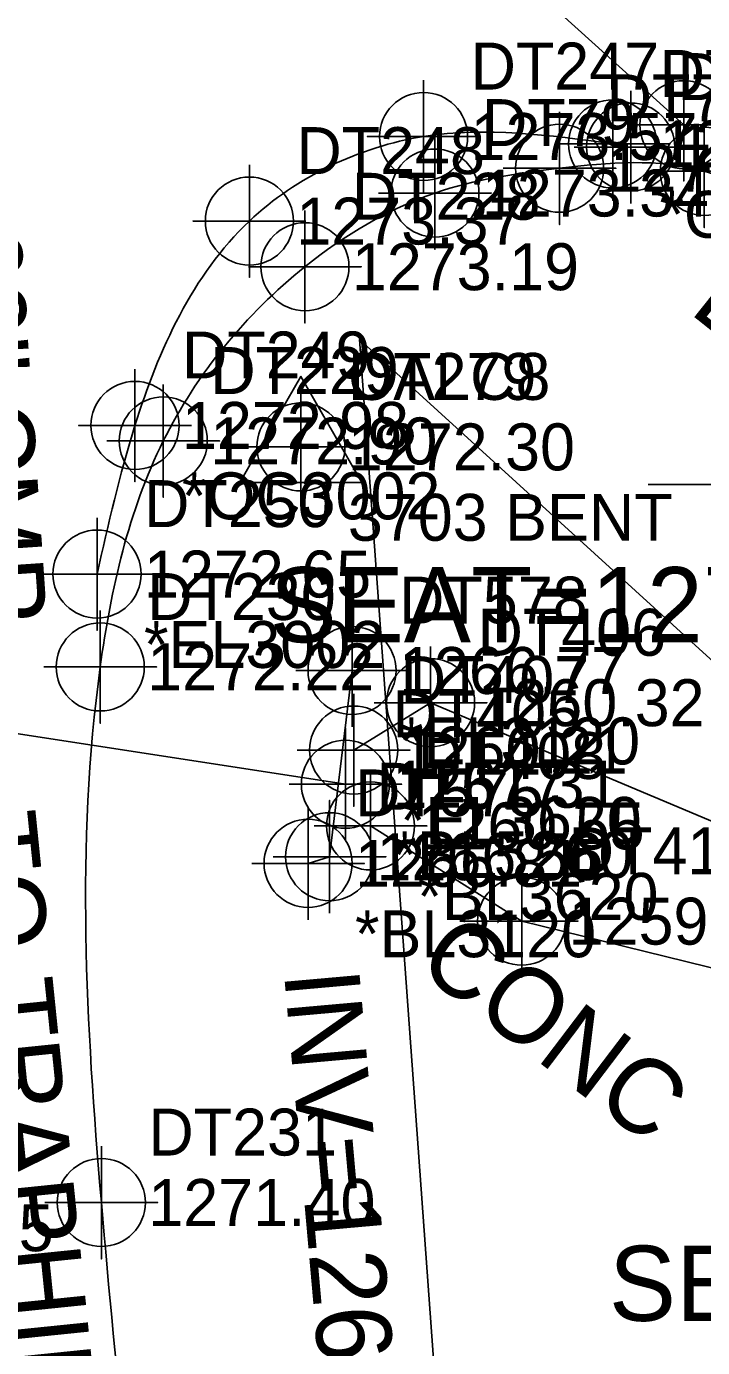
# Model space of a CAD drawing. Extents: x 1390773 to 1392296, y 959928 to 960736.
# Drawn here: x 1391507.3 to 1391543.3, y 960333 to 960403.3 of the extents above; entities that cross this region are included whole.
import ezdxf

# ---------------------------------------------------------------- set-up
doc = ezdxf.new("R2010")
doc.units = 0
for name, color, linetype in [('Cogo Default Point CELL', 7, 'Continuous'), ('COGO Default Point Elevation', 7, 'Continuous'), ('COGO Default Point Number', 7, 'Continuous'), ('Exist Hydro Jurisdictional Stream or Body of Water', 7, 'Continuous'), ('Exist Hydro Stream or Body of Water', 7, 'Continuous'), ('Exist Hydro Stream or Body of Water Cogo Comment', 7, 'Continuous'), ('Exist Hydro Stream or Body of Water Cogo Elevation', 7, 'Continuous'), ('Exist Hydro Stream or Body of Water Cogo Number', 7, 'Continuous'), ('Exist Hydro Stream or Body of Water Cogo Point CELL', 7, 'Continuous'), ('Exist Other Culture Located Object Text', 7, 'Continuous'), ('Exist Right of Way Line', 7, 'Continuous'), ('Exist Right of Way Monument CELL', 7, 'Continuous'), ('Exist Right of Way Monument Cogo Comment', 7, 'Continuous'), ('Exist Right of Way Monument Cogo Elevation', 7, 'Continuous'), ('Exist Right of Way Monument Cogo Number', 7, 'Continuous'), ('Exist Roads EOP', 7, 'Continuous'), ('Exist Roads EOP Cogo Elevation', 7, 'Continuous'), ('Exist Roads EOP Cogo Number', 7, 'Continuous'), ('Exist Roads EOP Cogo Point CELL', 7, 'Continuous'), ('Exist Roads EOP Text', 7, 'Continuous'), ('Exist Roads EOT', 7, 'Continuous'), ('Exist Roads EOT Cogo Comment', 7, 'Continuous'), ('Exist Roads EOT Cogo Elevation', 7, 'Continuous'), ('Exist Roads EOT Cogo Number', 7, 'Continuous'), ('Exist Roads EOT Cogo Point CELL', 7, 'Continuous'), ('Exist Structure Major Bridge Seat Top Elevation', 7, 'Continuous'), ('Exist Structure Minor Head and End Wall', 7, 'Continuous'), ('Exist Structure Minor Head and End Wall Cogo Comment', 7, 'Continuous'), ('Exist Structure Minor Head and End Wall Cogo Elevation', 7, 'Continuous'), ('Exist Structure Minor Head and End Wall Cogo Number', 7, 'Continuous'), ('Exist Structure Minor Head and End Wall Cogo Point CELL', 7, 'Continuous'), ('Exist Structure Minor Head and End Wall Text', 7, 'Continuous'), ('Exist Structure Minor Pipes CMP 60 Inch', 7, 'Continuous'), ('Exist Structure Minor Pipes CMP 60 Inch Cogo Comment', 7, 'Continuous'), ('Exist Structure Minor Pipes CMP 60 Inch Cogo Elevation', 7, 'Continuous'), ('Exist Structure Minor Pipes CMP 60 Inch Cogo Number', 7, 'Continuous'), ('Exist Structure Minor Pipes CMP 60 Inch Cogo Point CELL', 7, 'Continuous'), ('Exist Structure Minor Pipes CMP 60 Inch Invert', 7, 'Continuous'), ('Exist Structure Minor Pipes CMP 60 Inch Text', 7, 'Continuous'), ('Exist Utilities Telephone Pole CELL', 7, 'Continuous')]:
    doc.layers.add(name, color=color, linetype=linetype)

msp = doc.modelspace()

# ---------------------------------------------------------------- linework, layer by layer
at = {"layer": 'Cogo Default Point CELL'}
for points in [[(1391539.491, 960399.874), (1391539.491, 960396.874)], [(1391536.491, 960396.874), (1391539.491, 960396.874)], [(1391539.491, 960396.874), (1391542.491, 960396.874)], [(1391539.491, 960396.874), (1391539.491, 960393.874)], [(1391521.941, 960383.908), (1391521.941, 960380.908)], [(1391518.941, 960380.908), (1391521.941, 960380.908)], [(1391521.941, 960380.908), (1391524.941, 960380.908)], [(1391521.941, 960380.908), (1391521.941, 960377.908)]]:
    msp.add_lwpolyline(points, dxfattribs=at)
for centre in [(1391539.491, 960396.874), (1391521.941, 960380.908)]:
    msp.add_circle(centre, 2.344, dxfattribs=at)
at = {"layer": 'Exist Hydro Jurisdictional Stream or Body of Water'}
msp.add_lwpolyline([(1391525.646, 960360.725), (1391533.691, 960355.656), (1391551.222, 960351.349), (1391566.005, 960349.028), (1391587.602, 960346.087), (1391590.063, 960325.761), (1391581.908, 960284.337), (1391574.185, 960247.222), (1391569.673, 960235.504)], dxfattribs=at)
at = {"layer": 'Exist Hydro Stream or Body of Water'}
msp.add_lwpolyline([(1391589.108, 960351.82), (1391588.85, 960350.646), (1391564.84, 960352.852), (1391552.616, 960357.272), (1391528.84, 960367.287), (1391524.75, 960364.767)], dxfattribs=at)
at = {"layer": 'Exist Hydro Stream or Body of Water Cogo Point CELL'}
for points in [[(1391525.84, 960367.287), (1391531.84, 960367.287), (1391528.84, 960367.287), (1391528.84, 960364.287), (1391528.84, 960370.287)], [(1391521.75, 960364.767), (1391527.75, 960364.767), (1391524.75, 960364.767), (1391524.75, 960361.767), (1391524.75, 960367.767)], [(1391522.646, 960360.725), (1391528.646, 960360.725), (1391525.646, 960360.725), (1391525.646, 960357.725), (1391525.646, 960363.725)], [(1391530.691, 960355.656), (1391536.691, 960355.656), (1391533.691, 960355.656), (1391533.691, 960352.656), (1391533.691, 960358.656)]]:
    msp.add_lwpolyline(points, dxfattribs=at)
for centre in [(1391528.84, 960367.287), (1391524.75, 960364.767), (1391525.646, 960360.725), (1391533.691, 960355.656)]:
    msp.add_circle(centre, 2.344, dxfattribs=at)
at = {"layer": 'Exist Right of Way Line'}
for p, q in [((1391525.055, 960386.628), (1391657.467, 960265.902)), ((1391530.522, 960311.417), (1391525.055, 960386.628))]:
    msp.add_line(p, q, dxfattribs=at)
at = {"layer": 'Exist Right of Way Monument CELL'}
msp.add_line((1391521.941, 960380.908), (1391521.941, 960380.908), dxfattribs=at)
msp.add_lwpolyline([(1391518.692, 960379.019), (1391521.941, 960384.658), (1391525.189, 960379.018)], close=True, dxfattribs=at)
at = {"layer": 'Exist Roads EOP'}
msp.add_spline([(1391553.715, 960387.967), (1391548.413, 960392.843), (1391543.408, 960395.581), (1391535.709, 960395.746), (1391529.074, 960394.424), (1391522.155, 960390.501), (1391514.618, 960381.223), (1391511.262, 960369.19), (1391511.324, 960340.675), (1391514.177, 960312.818)], degree=3, dxfattribs=at)
at = {"layer": 'Exist Roads EOP Cogo Point CELL'}
for points in [[(1391535.709, 960398.746), (1391535.709, 960392.746), (1391535.709, 960395.746), (1391538.709, 960395.746), (1391532.709, 960395.746)], [(1391543.408, 960398.581), (1391543.408, 960392.581), (1391543.408, 960395.581), (1391546.408, 960395.581), (1391540.408, 960395.581)], [(1391529.074, 960397.424), (1391529.074, 960391.424), (1391529.074, 960394.424), (1391532.074, 960394.424), (1391526.074, 960394.424)], [(1391522.155, 960393.501), (1391522.155, 960387.501), (1391522.155, 960390.501), (1391525.155, 960390.501), (1391519.155, 960390.501)], [(1391514.618, 960384.223), (1391514.618, 960378.223), (1391514.618, 960381.223), (1391517.618, 960381.223), (1391511.618, 960381.223)], [(1391511.262, 960372.19), (1391511.262, 960366.19), (1391511.262, 960369.19), (1391514.262, 960369.19), (1391508.262, 960369.19)], [(1391511.324, 960343.675), (1391511.324, 960337.675), (1391511.324, 960340.675), (1391514.324, 960340.675), (1391508.324, 960340.675)]]:
    msp.add_lwpolyline(points, dxfattribs=at)
for centre in [(1391535.709, 960395.746), (1391543.408, 960395.581), (1391529.074, 960394.424), (1391522.155, 960390.501), (1391514.618, 960381.223), (1391511.262, 960369.19), (1391511.324, 960340.675)]:
    msp.add_circle(centre, 2.344, dxfattribs=at)
at = {"layer": 'Exist Roads EOT'}
msp.add_lwpolyline([(1391542.319, 960398.059), (1391518.576, 960419.517), (1391494.192, 960441.585), (1391465.739, 960467.932), (1391455.599, 960477.451)], dxfattribs=at)
msp.add_spline([(1391511.094, 960374.137), (1391513.113, 960382.05), (1391519.201, 960392.933), (1391528.47, 960397.434), (1391538.533, 960397.042)], degree=3, dxfattribs=at)
at = {"layer": 'Exist Roads EOT Cogo Point CELL'}
for points in [[(1391542.319, 960401.059), (1391542.319, 960395.059), (1391542.319, 960398.059), (1391539.319, 960398.059), (1391545.319, 960398.059)], [(1391528.47, 960400.434), (1391528.47, 960394.434), (1391528.47, 960397.434), (1391525.47, 960397.434), (1391531.47, 960397.434)], [(1391538.533, 960400.042), (1391538.533, 960394.042), (1391538.533, 960397.042), (1391535.533, 960397.042), (1391541.533, 960397.042)], [(1391519.201, 960395.933), (1391519.201, 960389.933), (1391519.201, 960392.933), (1391516.201, 960392.933), (1391522.201, 960392.933)], [(1391513.113, 960385.05), (1391513.113, 960379.05), (1391513.113, 960382.05), (1391510.113, 960382.05), (1391516.113, 960382.05)], [(1391511.094, 960377.137), (1391511.094, 960371.137), (1391511.094, 960374.137), (1391508.094, 960374.137), (1391514.094, 960374.137)]]:
    msp.add_lwpolyline(points, dxfattribs=at)
for centre in [(1391542.319, 960398.059), (1391528.47, 960397.434), (1391538.533, 960397.042), (1391519.201, 960392.933), (1391513.113, 960382.05), (1391511.094, 960374.137)]:
    msp.add_circle(centre, 2.344, dxfattribs=at)
at = {"layer": 'Exist Structure Minor Head and End Wall'}
msp.add_lwpolyline([(1391522.324, 960358.734), (1391523.466, 960359.087), (1391524.665, 960369.001)], dxfattribs=at)
at = {"layer": 'Exist Structure Minor Head and End Wall Cogo Point CELL'}
for points in [[(1391521.665, 960369.001), (1391527.665, 960369.001), (1391524.665, 960369.001), (1391524.665, 960372.001), (1391524.665, 960366.001)], [(1391520.466, 960359.087), (1391526.466, 960359.087), (1391523.466, 960359.087), (1391523.466, 960362.087), (1391523.466, 960356.087)], [(1391519.324, 960358.734), (1391525.324, 960358.734), (1391522.324, 960358.734), (1391522.324, 960361.734), (1391522.324, 960355.734)]]:
    msp.add_lwpolyline(points, dxfattribs=at)
for centre in [(1391524.665, 960369.001), (1391523.466, 960359.087), (1391522.324, 960358.734)]:
    msp.add_circle(centre, 2.344, dxfattribs=at)
at = {"layer": 'Exist Structure Minor Pipes CMP 60 Inch'}
msp.add_line((1391524.311, 960362.945), (1391475.363, 960370.472), dxfattribs=at)
at = {"layer": 'Exist Structure Minor Pipes CMP 60 Inch Cogo Point CELL'}
msp.add_lwpolyline([(1391524.311, 960365.945), (1391524.311, 960359.945), (1391524.311, 960362.945), (1391527.311, 960362.945), (1391521.311, 960362.945)], dxfattribs=at)
msp.add_circle((1391524.311, 960362.945), 2.344, dxfattribs=at)
at = {"layer": 'Exist Utilities Telephone Pole CELL'}
msp.add_line((1391540.422, 960378.907), (1391551.759, 960378.907), dxfattribs=at)

# ---------------------------------------------------------------- texts
at = {"layer": 'COGO Default Point Elevation'}
for s, p in [('1273.69', (1391541.991, 960395.624)), ('1272.30', (1391524.441, 960379.658))]:
    msp.add_text(s, height=2.5, dxfattribs=at).set_placement(p)
at = {"layer": 'COGO Default Point Number'}
for s, p in [('DT245', (1391541.991, 960399.374)), ('CALC8', (1391524.441, 960383.408))]:
    msp.add_text(s, height=2.5, dxfattribs=at).set_placement(p)
at = {"layer": 'Exist Hydro Stream or Body of Water Cogo Comment'}
for s, p in [('*EL3620', (1391527.25, 960359.767)), ('*BL3620', (1391528.146, 960355.725))]:
    msp.add_text(s, height=2.5, dxfattribs=at).set_placement(p)
at = {"layer": 'Exist Hydro Stream or Body of Water Cogo Elevation'}
for s, p in [('1260.32', (1391531.34, 960366.037)), ('1260.21', (1391527.25, 960363.517)), ('1260.55', (1391528.146, 960359.475)), ('1259.88', (1391536.191, 960354.406))]:
    msp.add_text(s, height=2.5, dxfattribs=at).set_placement(p)
at = {"layer": 'Exist Hydro Stream or Body of Water Cogo Number'}
for s, p in [('DT406', (1391531.34, 960369.787)), ('DT407', (1391527.25, 960367.267)), ('DT408', (1391528.146, 960363.225)), ('DT410', (1391536.191, 960358.156))]:
    msp.add_text(s, height=2.5, dxfattribs=at).set_placement(p)
at = {"layer": 'Exist Other Culture Located Object Text'}
msp.add_text('BD1', height=4, rotation=321.50919, dxfattribs=at).set_placement((1391542.533, 960388.092))
at = {"layer": 'Exist Right of Way Monument Cogo Comment'}
msp.add_text('3703 BENT', height=2.5, dxfattribs=at).set_placement((1391524.441, 960375.908))
at = {"layer": 'Exist Right of Way Monument Cogo Elevation'}
msp.add_text('1272.30', height=2.5, dxfattribs=at).set_placement((1391524.441, 960379.658))
at = {"layer": 'Exist Right of Way Monument Cogo Number'}
msp.add_text('DT279', height=2.5, dxfattribs=at).set_placement((1391524.441, 960383.408))
at = {"layer": 'Exist Roads EOP Cogo Elevation'}
for s, p in [('1273.48', (1391538.209, 960394.496)), ('1273.34', (1391531.574, 960393.174)), ('1273.19', (1391524.655, 960389.251)), ('1272.90', (1391517.118, 960379.973)), ('1272.22', (1391513.762, 960367.94)), ('1271.40', (1391513.824, 960339.425)), ('1271.65', (1391496.699, 960338.083))]:
    msp.add_text(s, height=2.5, dxfattribs=at).set_placement(p)
at = {"layer": 'Exist Roads EOP Cogo Number'}
for s, p in [('DT78', (1391538.209, 960398.246)), ('DT79', (1391531.574, 960396.924)), ('DT228', (1391524.655, 960393.001)), ('DT229', (1391517.118, 960383.723)), ('DT230', (1391513.762, 960371.69)), ('DT231', (1391513.824, 960343.175))]:
    msp.add_text(s, height=2.5, dxfattribs=at).set_placement(p)
at = {"layer": 'Exist Roads EOP Text'}
msp.add_text('TO TRAPHILL RD. SR 1002', height=4, rotation=275.84761, dxfattribs=at).set_placement((1391503.821, 960361.279))
at = {"layer": 'Exist Roads EOT Cogo Comment'}
for s, p in [('*OC3002', (1391541.033, 960392.042)), ('*OC3002', (1391515.613, 960377.05)), ('*EL3002', (1391513.594, 960369.137))]:
    msp.add_text(s, height=2.5, dxfattribs=at).set_placement(p)
at = {"layer": 'Exist Roads EOT Cogo Elevation'}
for s, p in [('1273.57', (1391530.97, 960396.184)), ('1273.69', (1391541.033, 960395.792)), ('1273.37', (1391521.701, 960391.683)), ('1272.98', (1391515.613, 960380.8)), ('1272.65', (1391513.594, 960372.887))]:
    msp.add_text(s, height=2.5, dxfattribs=at).set_placement(p)
at = {"layer": 'Exist Roads EOT Cogo Number'}
for s, p in [('DT247', (1391530.97, 960399.934)), ('DT246', (1391541.033, 960399.542)), ('DT248', (1391521.701, 960395.433)), ('DT249', (1391515.613, 960384.55)), ('DT250', (1391513.594, 960376.637))]:
    msp.add_text(s, height=2.5, dxfattribs=at).set_placement(p)
at = {"layer": 'Exist Structure Major Bridge Seat Top Elevation'}
for s, p in [("SEAT=1271.31'", (1391520.286, 960370.505)), ("SEAT=1271.29'", (1391538.334, 960334.373))]:
    msp.add_text(s, height=4, dxfattribs=at).set_placement(p)
at = {"layer": 'Exist Structure Minor Head and End Wall Cogo Comment'}
for s, p in [('*EL3120', (1391527.165, 960364.001)), ('*BL3120', (1391524.824, 960353.734))]:
    msp.add_text(s, height=2.5, dxfattribs=at).set_placement(p)
at = {"layer": 'Exist Structure Minor Head and End Wall Cogo Elevation'}
for s, p in [('1266.77', (1391527.165, 960367.751)), ('1266.81', (1391524.824, 960357.484)), ('1266.56', (1391525.966, 960357.837))]:
    msp.add_text(s, height=2.5, dxfattribs=at).set_placement(p)
at = {"layer": 'Exist Structure Minor Head and End Wall Cogo Number'}
for s, p in [('DT578', (1391527.165, 960371.501)), ('DT577', (1391525.966, 960361.587)), ('DT575', (1391524.824, 960361.234))]:
    msp.add_text(s, height=2.5, dxfattribs=at).set_placement(p)
at = {"layer": 'Exist Structure Minor Head and End Wall Text'}
msp.add_text('CONC', height=4, rotation=322.82359, dxfattribs=at).set_placement((1391527.972, 960353.165))
at = {"layer": 'Exist Structure Minor Pipes CMP 60 Inch Cogo Comment'}
msp.add_text('*BL5260', height=2.5, dxfattribs=at).set_placement((1391526.811, 960357.945))
at = {"layer": 'Exist Structure Minor Pipes CMP 60 Inch Cogo Elevation'}
msp.add_text('1261.31', height=2.5, dxfattribs=at).set_placement((1391526.811, 960361.695))
at = {"layer": 'Exist Structure Minor Pipes CMP 60 Inch Cogo Number'}
msp.add_text('DT405', height=2.5, dxfattribs=at).set_placement((1391526.811, 960365.445))
at = {"layer": 'Exist Structure Minor Pipes CMP 60 Inch Invert'}
msp.add_text("INV=1261.31'", height=4, rotation=275.07973, dxfattribs=at).set_placement((1391521.038, 960352.923))
at = {"layer": 'Exist Structure Minor Pipes CMP 60 Inch Text'}
msp.add_text('60" CMP', height=4, rotation=273.91364, dxfattribs=at).set_placement((1391503.005, 960392.504))

doc.saveas('drawing.dxf')
